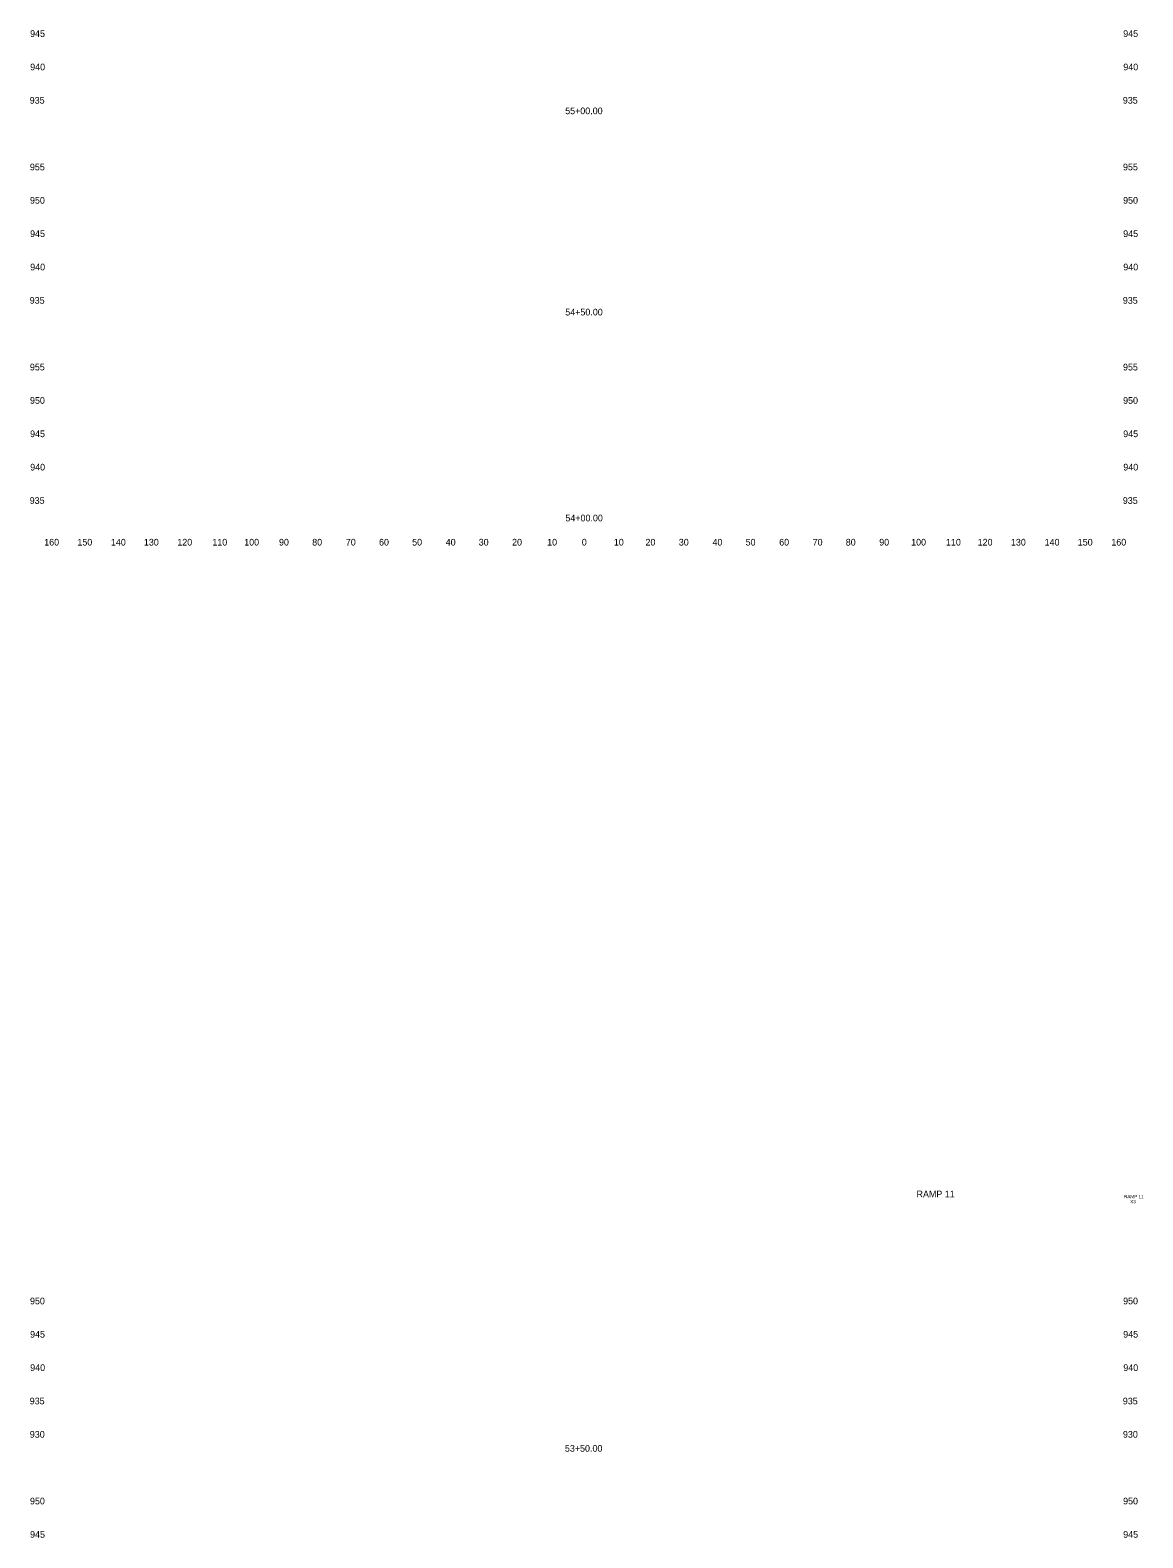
# Model space of a CAD drawing. Extents: x 4994 to 5843, y 4997 to 8804.
# Drawn here: x 4993.9 to 5327.6, y 5900 to 6352 of the extents above; entities that cross this region are included whole.
import ezdxf

# ---------------------------------------------------------------- set-up
doc = ezdxf.new("R2010")
doc.units = 0
for name, color, linetype in [('RD_SHT_ID', 7, 'Continuous'), ('RD_XS_TX_Offset', 7, 'Continuous'), ('RD_XS_TX_Station', 7, 'Continuous')]:
    doc.layers.add(name, color=color, linetype=linetype)

msp = doc.modelspace()

# ---------------------------------------------------------------- texts
at = {"layer": 'RD_SHT_ID'}
for s, height, p in [('RAMP 11', 2, (5259.69, 6002.06)), ('RAMP 11', 1, (5321.89, 6001.8)), ('X3', 1, (5323.74, 6000.3))]:
    msp.add_text(s, height=height, dxfattribs=at).set_placement(p)
at = {"layer": 'RD_XS_TX_Offset'}
for s, p in [('945', (4993.86, 6350)), ('945', (5321.66, 6350)), ('940', (4993.89, 6340)), ('940', (5321.69, 6340)), ('935', (4993.75, 6330)), ('935', (5321.55, 6330)), ('955', (4993.8, 6310)), ('955', (5321.6, 6310)), ('950', (4993.83, 6300)), ('950', (5321.63, 6300)), ('945', (4993.86, 6290)), ('945', (5321.66, 6290)), ('940', (4993.89, 6280)), ('940', (5321.69, 6280)), ('935', (4993.75, 6270)), ('935', (5321.55, 6270)), ('955', (4993.8, 6250)), ('955', (5321.6, 6250)), ('950', (4993.83, 6240)), ('950', (5321.63, 6240)), ('945', (4993.86, 6230)), ('945', (5321.66, 6230)), ('940', (4993.89, 6220)), ('940', (5321.69, 6220)), ('935', (4993.75, 6210)), ('935', (5321.55, 6210)), ('160', (4998.1, 6197.5)), ('150', (5008.04, 6197.5)), ('140', (5018.1, 6197.5)), ('130', (5027.99, 6197.5)), ('120', (5038.01, 6197.5)), ('110', (5048.51, 6197.5)), ('100', (5058.07, 6197.5)), ('90', (5068.5, 6197.5)), ('80', (5078.46, 6197.5)), ('70', (5088.54, 6197.5)), ('60', (5098.5, 6197.5)), ('50', (5108.43, 6197.5)), ('40', (5118.5, 6197.5)), ('30', (5128.39, 6197.5)), ('20', (5138.4, 6197.5)), ('10', (5148.91, 6197.5)), ('0', (5159.3, 6197.5)), ('0', (5159.3, 6197.5)), ('10', (5168.91, 6197.5)), ('20', (5178.4, 6197.5)), ('30', (5188.39, 6197.5)), ('40', (5198.5, 6197.5)), ('50', (5208.43, 6197.5)), ('60', (5218.5, 6197.5)), ('70', (5228.54, 6197.5)), ('80', (5238.46, 6197.5)), ('90', (5248.5, 6197.5)), ('100', (5258.07, 6197.5)), ('110', (5268.51, 6197.5)), ('120', (5278.01, 6197.5)), ('130', (5287.99, 6197.5)), ('140', (5298.1, 6197.5)), ('150', (5308.04, 6197.5)), ('160', (5318.1, 6197.5)), ('950', (4993.83, 5970)), ('950', (5321.63, 5970)), ('945', (4993.86, 5960)), ('945', (5321.66, 5960)), ('940', (4993.89, 5950)), ('940', (5321.69, 5950)), ('935', (4993.75, 5940)), ('935', (5321.55, 5940)), ('930', (4993.78, 5930)), ('930', (5321.58, 5930)), ('950', (4993.83, 5910)), ('950', (5321.63, 5910)), ('945', (4993.86, 5900)), ('945', (5321.66, 5900))]:
    msp.add_text(s, height=2, dxfattribs=at).set_placement(p)
at = {"layer": 'RD_XS_TX_Station'}
for s, p in [('55+00.00', (5154.32, 6326.83)), ('54+50.00', (5154.35, 6266.49)), ('54+00.00', (5154.39, 6204.75)), ('53+50.00', (5154.24, 5925.8))]:
    msp.add_text(s, height=2, dxfattribs=at).set_placement(p)

doc.saveas('drawing.dxf')
